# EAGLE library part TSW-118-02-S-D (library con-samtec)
THROUGH-HOLE .025" SQ POST HEADER Source: Samtec TSW.pdf
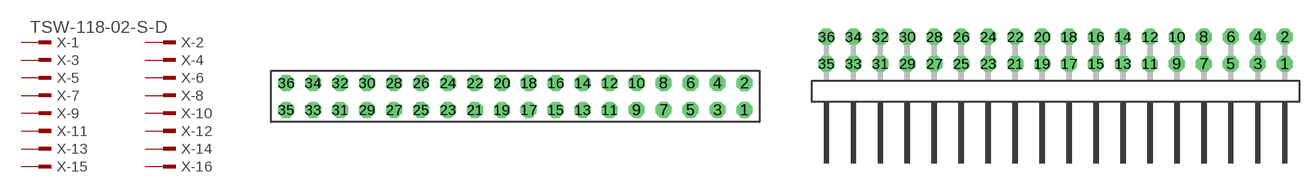
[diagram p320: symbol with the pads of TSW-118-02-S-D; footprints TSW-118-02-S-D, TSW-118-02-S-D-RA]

Designator prefix X; gates -1=MPINV -2=MPIN -3=MPIN -4=MPIN -5=MPIN -6=MPIN -7=MPIN -8=MPIN -9=MPIN -10=MPIN -11=MPIN -12=MPIN -13=MPIN -14=MPIN -15=MPIN -16=MPIN -17=MPIN -18=MPIN -19=MPIN -20=MPIN -21=MPIN -22=MPIN -23=MPIN -24=MPIN -25=MPIN -26=MPIN -27=MPIN -28=MPIN -29=MPIN -30=MPIN -31=MPIN -32=MPIN -33=MPIN -34=MPIN -35=MPIN -36=MPIN

## TSW-118-02-S-D (OC_FARNELL: unknown; OC_NEWARK: unknown)  [TSW-118-02-S-D]
1  -1:1  pas
2  -2:1  pas
3  -3:1  pas
4  -4:1  pas
5  -5:1  pas
6  -6:1  pas
7  -7:1  pas
8  -8:1  pas
9  -9:1  pas
10  -10:1  pas
11  -11:1  pas
12  -12:1  pas
13  -13:1  pas
14  -14:1  pas
15  -15:1  pas
16  -16:1  pas
17  -17:1  pas
18  -18:1  pas
19  -19:1  pas
20  -20:1  pas
21  -21:1  pas
22  -22:1  pas
23  -23:1  pas
24  -24:1  pas
25  -25:1  pas
26  -26:1  pas
27  -27:1  pas
28  -28:1  pas
29  -29:1  pas
30  -30:1  pas
31  -31:1  pas
32  -32:1  pas
33  -33:1  pas
34  -34:1  pas
35  -35:1  pas
36  -36:1  pas

## TSW-118-02-S-D-RA (OC_FARNELL: unknown; OC_NEWARK: unknown)  [TSW-118-02-S-D-RA]
Pads as for TSW-118-02-S-D

## Footprint TSW-118-02-S-D (pad centres in mm)
THROUGH-HOLE .025" SQ POST HEADER Source: Samtec TSW.pdf
drill 1 pad 1.5 octagon: 1 21.59,-1.27; 2 21.59,1.27; 3 19.05,-1.27; 4 19.05,1.27; 5 16.51,-1.27; 6 16.51,1.27; 7 13.97,-1.27; 8 13.97,1.27; 9 11.43,-1.27; 10 11.43,1.27; 11 8.89,-1.27; 12 8.89,1.27; 13 6.35,-1.27; 14 6.35,1.27; 15 3.81,-1.27; 16 3.81,1.27; 17 1.27,-1.27; 18 1.27,1.27; 19 -1.27,-1.27; 20 -1.27,1.27; 21 -3.81,-1.27; 22 -3.81,1.27; 23 -6.35,-1.27; 24 -6.35,1.27; 25 -8.89,-1.27; 26 -8.89,1.27; 27 -11.43,-1.27; 28 -11.43,1.27; 29 -13.97,-1.27; 30 -13.97,1.27; 31 -16.51,-1.27; 32 -16.51,1.27; 33 -19.05,-1.27; 34 -19.05,1.27; 35 -21.59,-1.27; 36 -21.59,1.27

## Footprint TSW-118-02-S-D-RA (pad centres in mm)
THROUGH-HOLE .025" SQ POST HEADER Source: Samtec TSW.pdf
drill 1 pad 1.5 octagon: 1 21.59,1.524; 2 21.59,4.064; 3 19.05,1.524; 4 19.05,4.064; 5 16.51,1.524; 6 16.51,4.064; 7 13.97,1.524; 8 13.97,4.064; 9 11.43,1.524; 10 11.43,4.064; 11 8.89,1.524; 12 8.89,4.064; 13 6.35,1.524; 14 6.35,4.064; 15 3.81,1.524; 16 3.81,4.064; 17 1.27,1.524; 18 1.27,4.064; 19 -1.27,1.524; 20 -1.27,4.064; 21 -3.81,1.524; 22 -3.81,4.064; 23 -6.35,1.524; 24 -6.35,4.064; 25 -8.89,1.524; 26 -8.89,4.064; 27 -11.43,1.524; 28 -11.43,4.064; 29 -13.97,1.524; 30 -13.97,4.064; 31 -16.51,1.524; 32 -16.51,4.064; 33 -19.05,1.524; 34 -19.05,4.064; 35 -21.59,1.524; 36 -21.59,4.064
